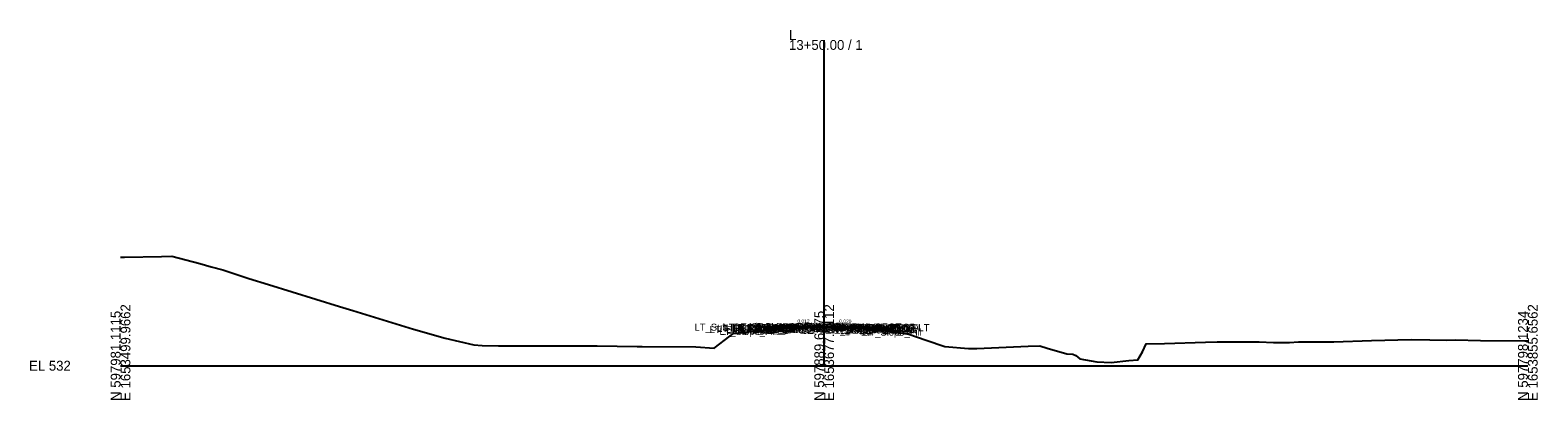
# Model space of a CAD drawing. Extents: x -26 to 403, y -10 to 6021.
# Drawn here: x -25.7 to 402.8, y 1990.3 to 2095.4 of the extents above; entities that cross this region are included whole.
import ezdxf

# ---------------------------------------------------------------- set-up
doc = ezdxf.new("R2010")
doc.units = 0
for name, color, linetype in [('Default', 7, 'Continuous'), ('Exist Cross Section Cell', 7, 'Continuous'), ('Exist XS Ground Line', 7, 'Continuous'), ('Prop CMT Pvmt Course 1', 7, 'Continuous'), ('Prop CMT Pvmt Course 1 Wedge', 7, 'Continuous'), ('Prop CMT Pvmt Course 2', 7, 'Continuous'), ('Prop CMT Pvmt Course 2 Wedge', 7, 'Continuous'), ('Prop CMT Pvmt Course 3', 7, 'Continuous'), ('Prop CMT Pvmt Course 3 Wedge', 7, 'Continuous'), ('Prop CMT Pvmt Surface', 7, 'Continuous'), ('Prop CMT Pvmt Surface Shoulder', 7, 'Continuous'), ('Prop CMT Pvmt Wedge Surface 1', 7, 'Continuous'), ('Prop CMT Pvmt Wedge Surface 2', 7, 'Continuous'), ('Prop CMT Pvmt Wedge Surface 3', 7, 'Continuous'), ('Prop CMT Shld Paved Course 1', 7, 'Continuous'), ('Prop CMT Shld Paved Course 2', 7, 'Continuous'), ('Prop CMT Shld Paved Course 3', 7, 'Continuous'), ('Prop CMT Slope Grass', 7, 'Continuous'), ('Prop CMT Subgrade Earthwork', 7, 'Continuous'), ('Prop XS Earthwork Shape', 7, 'Continuous'), ('Prop XS SE Text', 7, 'Continuous'), ('Prop XS Side Slope Text', 7, 'Continuous')]:
    doc.layers.add(name, color=color, linetype=linetype)

msp = doc.modelspace()

# ---------------------------------------------------------------- linework, layer by layer
at = {"layer": 'Exist Cross Section Cell'}
for p, q in [((200, 2000), (200, 2092.55)), ((0, 2000), (200, 2000)), ((200, 2000), (400, 2000))]:
    msp.add_line(p, q, dxfattribs=at)
at = {"layer": 'Exist XS Ground Line'}
msp.add_lwpolyline([(0, 2030.85), (0.45, 2030.83), (1.13, 2030.82), (11.65, 2031.08), (14.56, 2031.09), (22.5, 2029.08), (25.71, 2028.09), (29.08, 2027.23), (36.48, 2024.75), (42.03, 2023.05), (62.27, 2016.85), (64.17, 2016.26), (66.02, 2015.7), (83.29, 2010.39), (92.3, 2007.82), (100.37, 2005.89), (102.79, 2005.78), (107.4, 2005.61), (113.97, 2005.67), (135.51, 2005.69), (146.83, 2005.51), (148.24, 2005.5), (163.56, 2005.33), (168.7, 2005.02), (173.18, 2008.42), (174.2, 2009.19), (175.05, 2009.26), (185.7, 2010.4), (188.7, 2010.58), (198.78, 2010.88), (200, 2010.92), (200.52, 2010.93), (211.46, 2010.71), (212.2, 2010.69), (212.45, 2010.65), (217.77, 2009.93), (218.54, 2009.82), (224.03, 2009.01), (229, 2007.25), (234.31, 2005.47), (240.98, 2004.92), (243.39, 2004.91), (257.97, 2005.54), (261.33, 2005.66), (263.34, 2005), (269, 2003.36), (270.71, 2003.27), (271.53, 2002.89), (272.68, 2001.96), (277.47, 2001.06), (281.6, 2000.94), (286.55, 2001.47), (289.11, 2001.65), (290.46, 2003.96), (291.52, 2006.22), (296.71, 2006.31), (308.42, 2006.69), (311.71, 2006.8), (323.67, 2006.79), (327.73, 2006.61), (332.27, 2006.58), (334.77, 2006.78), (344.84, 2006.83), (355.53, 2007.19), (366.85, 2007.48), (372.13, 2007.35), (376.74, 2007.28), (379.4, 2007.35), (386.51, 2007.17), (399.1, 2007.07), (400, 2007.1)], dxfattribs=at)
at = {"layer": 'Prop CMT Pvmt Course 1'}
for points in [[(200, 2011.25), (188, 2011.1)], [(188, 2011.1), (188, 2010.89)], [(188, 2010.89), (188.7, 2010.9)], [(188.7, 2010.9), (200, 2011.04)], [(188.7, 2010.9), (188.7, 2010.9)], [(200, 2011.04), (200, 2011.25)], [(200, 2011.25), (212, 2011.01)], [(200, 2011.04), (200, 2011.25)], [(200, 2011.04), (200, 2011.04), (200, 2011.04)], [(212, 2010.8), (200, 2011.04)], [(200, 2011.04), (200, 2011.04), (200, 2011.04)], [(212, 2011.01), (212, 2010.8), (212, 2010.8), (212, 2010.8)]]:
    msp.add_lwpolyline(points, dxfattribs=at)
at = {"layer": 'Prop CMT Pvmt Course 1 Wedge'}
for points in [[(188.7, 2010.9), (198.78, 2011.02), (200, 2011.04)], [(200, 2010.92), (199.86, 2010.91), (198.78, 2010.9), (188.7, 2010.78)], [(188.7, 2010.9), (188.7, 2010.9)], [(188.7, 2010.78), (188.7, 2010.9)], [(188.7, 2010.78), (188.7, 2010.78)], [(200, 2011.04), (200, 2010.92)], [(200, 2011.04), (200.52, 2011.03), (211.46, 2010.81), (212, 2010.8)], [(200, 2010.92), (200, 2011.04)], [(212, 2010.7), (211.46, 2010.71), (200.52, 2010.93), (200, 2010.92)], [(212, 2010.8), (212, 2010.7)]]:
    msp.add_lwpolyline(points, dxfattribs=at)
at = {"layer": 'Prop CMT Pvmt Course 2'}
for points in [[(188.7, 2010.9), (188, 2010.89)], [(188, 2010.89), (188, 2010.69)], [(188, 2010.69), (188.7, 2010.69)], [(188.7, 2010.69), (188.7, 2010.9)], [(212, 2010.59), (212, 2010.59), (212, 2010.8), (212, 2010.8)], [(212, 2010.8), (212, 2010.59)]]:
    msp.add_lwpolyline(points, dxfattribs=at)
at = {"layer": 'Prop CMT Pvmt Course 2 Wedge'}
for points in [[(188.7, 2010.9), (198.78, 2011.02), (200, 2011.04)], [(200, 2010.92), (198.78, 2010.88), (195.37, 2010.77), (188.7, 2010.69)], [(188.7, 2010.9), (188.7, 2010.9)], [(188.7, 2010.69), (188.7, 2010.9)], [(188.7, 2010.69), (188.7, 2010.69)], [(200, 2011.04), (200, 2010.92)], [(200, 2011.04), (200.52, 2011.03), (211.46, 2010.81), (212, 2010.8)], [(200, 2010.92), (200, 2011.04)], [(212, 2010.7), (211.46, 2010.71), (200.52, 2010.93), (200, 2010.92)], [(212, 2010.8), (212, 2010.7)]]:
    msp.add_lwpolyline(points, dxfattribs=at)
at = {"layer": 'Prop CMT Pvmt Course 3'}
for points in [[(188.7, 2010.69), (188, 2010.69)], [(188, 2010.69), (188, 2010.35)], [(188, 2010.35), (188.7, 2010.36)], [(188.7, 2010.36), (188.7, 2010.69)], [(212, 2010.59), (212, 2010.59), (212, 2010.26), (212, 2010.26)], [(212, 2010.26), (212, 2010.59)]]:
    msp.add_lwpolyline(points, dxfattribs=at)
at = {"layer": 'Prop CMT Pvmt Course 3 Wedge'}
for points in [[(188.7, 2010.69), (195.37, 2010.77)], [(195.37, 2010.77), (188.7, 2010.58)], [(188.7, 2010.69), (188.7, 2010.69)], [(188.7, 2010.58), (188.7, 2010.69)], [(188.7, 2010.58), (188.7, 2010.58)]]:
    msp.add_lwpolyline(points, dxfattribs=at)
at = {"layer": 'Prop CMT Pvmt Surface'}
for points in [[(200, 2011.25), (188, 2011.1)], [(200, 2011.25), (212, 2011.01)]]:
    msp.add_lwpolyline(points, dxfattribs=at)
at = {"layer": 'Prop CMT Pvmt Surface Shoulder'}
for points in [[(188, 2011.1), (184, 2011.05)], [(212, 2011.01), (216, 2010.93)]]:
    msp.add_lwpolyline(points, dxfattribs=at)
at = {"layer": 'Prop CMT Pvmt Wedge Surface 1'}
for points in [[(188, 2010.89), (188, 2011.1)], [(188.7, 2010.9), (188, 2010.89)], [(200, 2011.04), (188.7, 2010.9)], [(188.7, 2010.9), (188.7, 2010.9)], [(200, 2011.25), (200, 2011.04), (200, 2011.04), (200, 2011.04)], [(200, 2011.25), (200, 2011.04), (200, 2011.04), (200, 2011.04)], [(200, 2011.04), (212, 2010.8)], [(212, 2010.8), (212, 2011.01)], [(212, 2010.8), (212, 2010.8), (212, 2010.8)]]:
    msp.add_lwpolyline(points, dxfattribs=at)
at = {"layer": 'Prop CMT Pvmt Wedge Surface 2'}
for points in [[(188, 2010.89), (188, 2011.1)], [(200, 2011.04), (188, 2010.89)], [(200, 2011.25), (200, 2011.04)], [(200, 2011.25), (200, 2011.04)], [(200, 2011.04), (212, 2010.8)], [(212, 2010.8), (212, 2011.01)]]:
    msp.add_lwpolyline(points, dxfattribs=at)
at = {"layer": 'Prop CMT Pvmt Wedge Surface 3'}
for points in [[(188, 2010.69), (188, 2011.1)], [(200, 2010.83), (188, 2010.69)], [(200, 2011.25), (200, 2010.83)], [(200, 2011.25), (200, 2010.83)], [(200, 2010.83), (212, 2010.59)], [(212, 2010.59), (212, 2011.01)]]:
    msp.add_lwpolyline(points, dxfattribs=at)
at = {"layer": 'Prop CMT Shld Paved Course 1'}
for points in [[(188, 2011.1), (184, 2011.05), (183.79, 2010.84)], [(183.79, 2010.84), (188, 2010.89)], [(188, 2010.89), (188, 2011.1)], [(212, 2011.01), (216, 2010.93), (216.21, 2010.71)], [(212, 2010.8), (212, 2011.01)], [(216.21, 2010.71), (212, 2010.8)]]:
    msp.add_lwpolyline(points, dxfattribs=at)
at = {"layer": 'Prop CMT Shld Paved Course 2'}
for points in [[(188, 2010.89), (183.79, 2010.84), (183.58, 2010.63)], [(183.58, 2010.63), (188, 2010.69)], [(188, 2010.69), (188, 2010.89)], [(212, 2010.8), (216.21, 2010.71), (216.43, 2010.5)], [(212, 2010.59), (212, 2010.8)], [(216.43, 2010.5), (212, 2010.59)]]:
    msp.add_lwpolyline(points, dxfattribs=at)
at = {"layer": 'Prop CMT Shld Paved Course 3'}
for points in [[(183.58, 2010.63), (183.24, 2010.3)], [(183.24, 2010.3), (188, 2010.35)], [(188, 2010.69), (183.58, 2010.63)], [(183.58, 2010.63), (183.58, 2010.63)], [(188, 2010.35), (188, 2010.69)], [(212, 2010.59), (216.43, 2010.5)], [(212, 2010.26), (212, 2010.59)], [(216.77, 2010.16), (212, 2010.26)], [(216.43, 2010.5), (216.43, 2010.5)], [(216.43, 2010.5), (216.77, 2010.16)]]:
    msp.add_lwpolyline(points, dxfattribs=at)
at = {"layer": 'Prop CMT Slope Grass'}
for points in [[(184, 2011.05), (182, 2010.91), (179.7, 2009.76)], [(216, 2010.93), (218, 2010.77), (220.46, 2009.54)]]:
    msp.add_lwpolyline(points, dxfattribs=at)
at = {"layer": 'Prop CMT Subgrade Earthwork'}
for points in [[(183.24, 2010.3), (182.58, 2010.95)], [(188, 2010.35), (183.24, 2010.3)], [(188.7, 2010.36), (188, 2010.35)], [(188.7, 2010.36), (188.72, 2010.58)], [(212, 2010.26), (211.98, 2010.7)], [(212, 2010.26), (212, 2010.26)], [(212, 2010.26), (216.77, 2010.16)], [(216.77, 2010.16), (217.42, 2010.81)]]:
    msp.add_lwpolyline(points, dxfattribs=at)
at = {"layer": 'Prop XS Earthwork Shape'}
for points in [[(182, 2010.91), (179.7, 2009.76), (184.89, 2010.32), (183.24, 2010.3), (182.58, 2010.95)], [(182, 2010.91), (179.7, 2009.76), (184.89, 2010.32), (183.24, 2010.3), (182.58, 2010.95)], [(182, 2010.91), (179.7, 2009.76), (184.89, 2010.32), (183.24, 2010.3), (182.58, 2010.95)], [(188.7, 2010.9), (200, 2011.04), (212, 2010.8), (212, 2011.01), (216, 2010.93), (217.42, 2010.81), (216.77, 2010.16), (215.94, 2010.18), (212.45, 2010.65), (212.2, 2010.69), (211.98, 2010.7), (211.46, 2010.71), (200.52, 2010.93), (200, 2010.92), (198.78, 2010.88), (188.72, 2010.58), (188.7, 2010.58), (185.7, 2010.4), (184.89, 2010.32), (183.24, 2010.3), (182.58, 2010.95), (184, 2011.05), (188, 2011.1), (188, 2010.89)], [(188.7, 2010.9), (200, 2011.04), (212, 2010.8), (212, 2011.01), (216, 2010.93), (217.42, 2010.81), (216.77, 2010.16), (215.94, 2010.18), (212.45, 2010.65), (212.2, 2010.69), (211.98, 2010.7), (211.46, 2010.71), (200.52, 2010.93), (200, 2010.92), (198.78, 2010.88), (188.72, 2010.58), (188.7, 2010.58), (185.7, 2010.4), (184.89, 2010.32), (183.24, 2010.3), (182.58, 2010.95), (184, 2011.05), (188, 2011.1), (188, 2010.89)], [(188.7, 2010.9), (200, 2011.04), (212, 2010.8), (212, 2011.01), (216, 2010.93), (217.42, 2010.81), (216.77, 2010.16), (215.94, 2010.18), (212.45, 2010.65), (212.2, 2010.69), (211.98, 2010.7), (211.46, 2010.71), (200.52, 2010.93), (200, 2010.92), (198.78, 2010.88), (188.72, 2010.58), (188.7, 2010.58), (185.7, 2010.4), (184.89, 2010.32), (183.24, 2010.3), (182.58, 2010.95), (184, 2011.05), (188, 2011.1), (188, 2010.89)], [(188.7, 2010.36), (188.72, 2010.58), (188.7, 2010.58), (185.7, 2010.4), (184.89, 2010.32), (188, 2010.35)], [(188.7, 2010.36), (188.72, 2010.58), (188.7, 2010.58), (185.7, 2010.4), (184.89, 2010.32), (188, 2010.35)], [(188.7, 2010.36), (188.72, 2010.58), (188.7, 2010.58), (185.7, 2010.4), (184.89, 2010.32), (188, 2010.35)], [(212, 2010.26), (211.98, 2010.7), (212.2, 2010.69), (212.45, 2010.65), (215.94, 2010.18)], [(212, 2010.26), (211.98, 2010.7), (212.2, 2010.69), (212.45, 2010.65), (215.94, 2010.18)], [(212, 2010.26), (211.98, 2010.7), (212.2, 2010.69), (212.45, 2010.65), (215.94, 2010.18)], [(218, 2010.77), (220.46, 2009.54), (218.54, 2009.82), (217.77, 2009.93), (215.94, 2010.18), (216.77, 2010.16), (217.42, 2010.81)], [(218, 2010.77), (220.46, 2009.54), (218.54, 2009.82), (217.77, 2009.93), (215.94, 2010.18), (216.77, 2010.16), (217.42, 2010.81)], [(218, 2010.77), (220.46, 2009.54), (218.54, 2009.82), (217.77, 2009.93), (215.94, 2010.18), (216.77, 2010.16), (217.42, 2010.81)]]:
    msp.add_lwpolyline(points, close=True, dxfattribs=at)

# ---------------------------------------------------------------- texts
at = {"layer": 'Default'}
for s, height, p in [('LT_Sub_Trench_Out_DLT', 2, (163.15, 2009.95)), ('LT_Sub_Trench_Out', 2, (167.45, 2009.3)), ('LT_PS3_Shelf_Out', 2, (169.56, 2009.63)), ('LT_Slope_Fill', 2, (170.22, 2008.76)), ('LT_GS_OS_CTL', 2, (171.37, 2009.91)), ('LT_PV_Sub_Tie_Out', 2, (173.66, 2009.58)), ('LT_PS3_OEOP', 2, (173.81, 2009.63)), ('LT_PS2_OEOP', 2, (174.03, 2009.84)), ('LT_PS1_OEOP', 2, (174.8, 2010.05)), ('LT_PV_OEEOP_EG', 2, (176.25, 2009.58)), ('LT_Sub_OEEOP', 2, (177.92, 2009.36)), ('LT_PV2_OEEOP', 2, (178.01, 2009.9)), ('LT_PV3_OEEOP', 2, (178.01, 2009.69)), ('LT_Sub_OEOT', 2, (178.08, 2009.35)), ('LT_PV2_OEOT', 2, (178.17, 2009.89)), ('LT_PV3_OEOT', 2, (178.17, 2009.69)), ('LT_PV1_OEEOP', 2, (178.58, 2009.9)), ('LT_PV1_OEOT', 2, (178.74, 2010.1)), ('LT_PV_EG_TestPt', 2, (180.76, 2009.74)), ('RT_PV_IEEOP_EG', 2, (188.14, 2009.92)), ('LT_PV_IEEOP_EG', 2, (188.19, 2009.92)), ('RT_PV2_IEEOP', 2, (189.91, 2010.04)), ('RT_PV3_IEEOP', 2, (189.91, 2009.83)), ('LT_PV2_IEEOP', 2, (189.95, 2010.04)), ('LT_PV3_IEEOP', 2, (189.95, 2009.83)), ('RT_PV1_IEEOP', 2, (190.47, 2010.04)), ('LT_PV1_IEEOP', 2, (190.52, 2010.04)), ('RT_PV_EG_TestPt', 2, (192.36, 2009.82)), ('PV2_PGL', 2, (193.91, 2010.04)), ('PV3_PGL', 2, (193.91, 2009.83)), ('PV1_PGL', 2, (194.47, 2010.25)), ('RT_PV_Sub_Tie_Out', 2, (196.88, 2009.7)), ('RT_Sub_Trench_Out_DLT', 2, (197.94, 2009.81)), ('RT_PV_OEEOP_EG', 2, (199.5, 2009.7)), ('RT_Sub_Trench_Out', 2, (200.92, 2009.16)), ('RT_Sub_OEEOP', 2, (201.17, 2009.26)), ('RT_PV2_OEEOP', 2, (201.26, 2009.8)), ('RT_PV3_OEEOP', 2, (201.26, 2009.59)), ('RT_PV1_OEEOP', 2, (201.83, 2009.8)), ('RT_Sub_OEOT', 2, (202.03, 2009.26)), ('RT_PV2_OEOT', 2, (202.13, 2009.8)), ('RT_PV3_OEOT', 2, (202.13, 2009.59)), ('RT_PS3_Shelf_Out', 2, (202.36, 2009.5)), ('RT_PV1_OEOT', 2, (202.69, 2010.01)), ('RT_PS2_OEOP', 2, (206.4, 2009.71)), ('RT_PS3_OEOP', 2, (206.61, 2009.5)), ('RT_PS1_OEOP', 2, (206.76, 2009.93)), ('RT_GS_OS_CTL', 2, (207.32, 2009.77)), ('RT_Slope_Fill', 2, (210.93, 2008.54)), ('-', 0.0001, (0, 2000))]:
    msp.add_text(s, height=height, dxfattribs=at).set_placement(p)
at = {"layer": 'Exist Cross Section Cell'}
for s, p in [('13+50.00 / 1', (190, 2089.75)), ('L', (190, 2092.55)), ('EL 532', (-26, 1998.6))]:
    msp.add_text(s, height=2.8, dxfattribs=at).set_placement(p)
for s, p in [('N 597981.1115', (0, 1990)), ('E 1653499.9662', (2.8, 1990)), ('N 597889.6175', (200, 1990)), ('E 1653677.8112', (202.8, 1990)), ('N 597798.1234', (400, 1990)), ('E 1653855.6562', (402.8, 1990))]:
    msp.add_text(s, height=2.8, rotation=90, dxfattribs=at).set_placement(p)
at = {"layer": 'Prop XS SE Text'}
for s, rotation, p in [('0.012', 0.6875, (192.4, 2012.16)), ('0.020', 358.8542, (204.27, 2012.16))]:
    msp.add_text(s, height=1, rotation=rotation, dxfattribs=at).set_placement(p)
at = {"layer": 'Prop XS Side Slope Text'}
for rotation, p in [(26.5651, (179.81, 2010.65)), (333.4349, (218.86, 2011.18))]:
    msp.add_text('2:1', height=1, rotation=rotation, dxfattribs=at).set_placement(p)

doc.saveas('drawing.dxf')
